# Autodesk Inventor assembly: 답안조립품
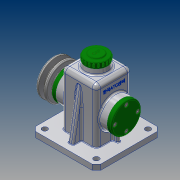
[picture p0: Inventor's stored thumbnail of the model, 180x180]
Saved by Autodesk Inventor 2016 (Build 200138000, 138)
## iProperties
Created: 2018-10
Part Number: 답안조립품
Material: 일반
Document SubType Name: Assembly
Designer: user
Author: user
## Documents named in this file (14)
- C:\Users\user\Desktop\481016V1005\답안조립품.iam
- C:\Users\user\Desktop\481016V1005\본체.ipt
- C:\Users\user\Desktop\481016V1005\481016V1005\베어링 15 x 35 x 11.ipt
- C:\Users\user\Desktop\481016V1005\481016V1005\축.ipt
- C:\Users\user\Desktop\481016V1005\481016V1005\멈춤링 15 x 1.ipt
- C:\Users\user\Desktop\481016V1005\481016V1005\뒤커버.ipt
- C:\Users\user\Desktop\481016V1005\481016V1005\앞커버.ipt
- C:\Users\user\Desktop\481016V1005\481016V1005\볼트 M4 x 10.ipt
- C:\Users\user\Desktop\481016V1005\481016V1005\상부캡.ipt
- C:\Users\user\Desktop\481016V1005\481016V1005\키 5 x 5 x 14.ipt
- C:\Users\user\Desktop\481016V1005\481016V1005\V-벨트풀리.ipt
- C:\Users\user\Desktop\481016V1005\481016V1005\볼트 M6 x 12.ipt
- C:\Users\user\Desktop\481016V1005\481016V1005\와셔.ipt
- C:\Users\user\Desktop\481016V1005\481016V1005\오일실 15 25 7.ipt
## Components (1 placed, 1 different names)
1. V-벨트풀리:1
